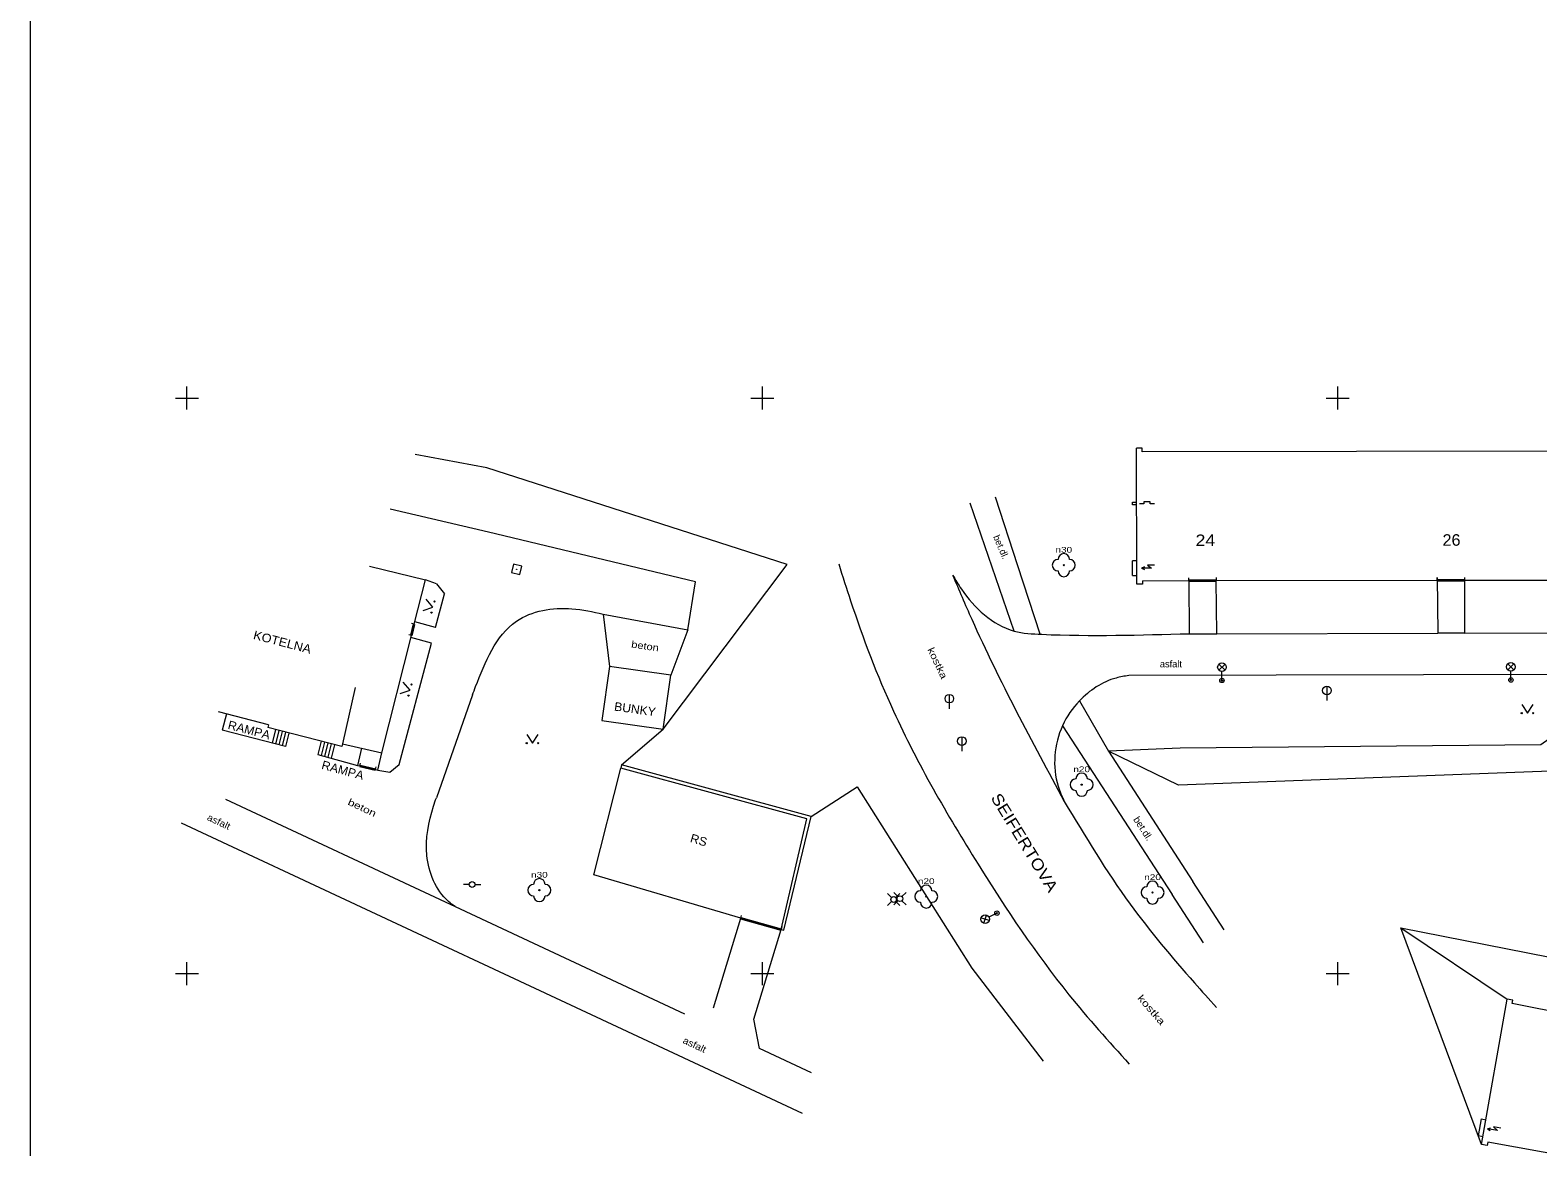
# Model space of a CAD drawing. Extents: x -670514 to -669423, y -1130798 to -1130123.
# Drawn here: x -670513.6 to -670382.6, y -1130515.1 to -1130418 of the extents above; entities that cross this region are included whole.
import ezdxf
from ezdxf.enums import TextEntityAlignment as Align

# ---------------------------------------------------------------- set-up
doc = ezdxf.new("R2010")
doc.units = 0
doc.header["$LTSCALE"] = 0.24
for name, color, linetype, lineweight in [('10', 7, 'Continuous', 13), ('11', 7, 'Continuous', 13), ('14', 7, 'Continuous', 13), ('22', 7, 'Continuous', 13), ('24', 7, 'Continuous', 13), ('26', 7, 'Continuous', 13), ('27', 7, 'Continuous', 13), ('28', 7, 'Continuous', 13), ('31', 7, 'Continuous', 13), ('33', 7, 'Continuous', 13), ('36', 7, 'Continuous', 13), ('45', 7, 'Continuous', 13), ('5', 7, 'Continuous', 13), ('6', 7, 'Continuous', 13), ('60', 7, 'Continuous', 13), ('61', 7, 'Continuous', 13), ('7', 7, 'Continuous', 13), ('8', 7, 'Continuous', 13)]:
    doc.layers.add(name, color=color, linetype=linetype, lineweight=lineweight)
for name, color, linetype in [('40', 7, 'Continuous'), ('41', 7, 'Continuous'), ('42', 7, 'Continuous'), ('44', 7, 'Continuous')]:
    doc.layers.add(name, color=color, linetype=linetype)

msp = doc.modelspace()

# ---------------------------------------------------------------- linework, layer by layer
at = {"layer": '10'}
for p, q in [((-670430.034, -1130464.686), (-670431.936, -1130459.135)), ((-670428.132, -1130470.237), (-670430.034, -1130464.686)), ((-670391.371, -1130465.583), (-670391.319, -1130470.435)), ((-670478.311, -1130466.135), (-670479.288, -1130465.803)), ((-670478.311, -1130466.135), (-670477.613, -1130467.004)), ((-670412.947, -1130465.855), (-670412.902, -1130470.474)), ((-670410.522, -1130470.472), (-670410.56, -1130465.852)), ((-670478.392, -1130469.935), (-670477.613, -1130467.004)), ((-670478.392, -1130469.935), (-670480.198, -1130469.455)), ((-670463.839, -1130468.773), (-670463.298, -1130473.326)), ((-670478.751, -1130471.289), (-670480.544, -1130470.813)), ((-670456.489, -1130470.127), (-670457.945, -1130474.07)), ((-670410.522, -1130470.472), (-670391.319, -1130470.435)), ((-670481.55, -1130481.827), (-670478.751, -1130471.289)), ((-670370.322, -1130474.001), (-670418.162, -1130474.105)), ((-670475.195, -1130475.776), (-670478.329, -1130484.72)), ((-670423.921, -1130478.465), (-670414.389, -1130493.139)), ((-670451.042, -1130510.045), (-670500.485, -1130486.945)), ((-670411.665, -1130497.332), (-670414.389, -1130493.139)), ((-670409.882, -1130496.203), (-670412.597, -1130492.004)), ((-670476.71, -1130494.173), (-670456.755, -1130503.484)), ((-670454.244, -1130502.991), (-670451.871, -1130495.185)), ((-670446.512, -1130512.161), (-670451.042, -1130510.045))]:
    msp.add_line(p, q, dxfattribs=at)
for points in [[(-670425.864, -1130470.526), (-670427.805, -1130464.571), (-670429.746, -1130458.616)], [(-670463.839, -1130468.773), (-670456.489, -1130470.127), (-670455.82, -1130465.971), (-670473.809, -1130461.637), (-670482.332, -1130459.664)], [(-670388.979, -1130465.827), (-670388.977, -1130470.429), (-670369.741, -1130470.406), (-670369.731, -1130465.796)], [(-670422.452, -1130476.308), (-670419.92, -1130480.678), (-670412.597, -1130492.004)], [(-670483.411, -1130482.326), (-670482.366, -1130482.497), (-670481.55, -1130481.827)], [(-670445.72, -1130508.635), (-670450.25, -1130506.519), (-670450.738, -1130503.963), (-670448.365, -1130496.157)]]:
    msp.add_lwpolyline(points, dxfattribs=at)
for points in [[(-670443.367, -1130464.39), (-670442.333, -1130467.627), (-670438.614, -1130477.191), (-670431.256, -1130490.506), (-670423.362, -1130501.834), (-670418.12, -1130507.871)], [(-670433.469, -1130465.379), (-670432.706, -1130466.601), (-670428.132, -1130470.237), (-670425.728, -1130470.526), (-670412.902, -1130470.474)], [(-670475.195, -1130475.776), (-670474.917, -1130475.064), (-670471.377, -1130469.388), (-670466.544, -1130468.3), (-670463.839, -1130468.773)], [(-670418.162, -1130474.105), (-670419.264, -1130474.323), (-670422.452, -1130476.308), (-670423.921, -1130478.465), (-670424.302, -1130483.718), (-670423.768, -1130485.048)], [(-670476.71, -1130494.173), (-670477.282, -1130493.729), (-670479.155, -1130489.729), (-670478.572, -1130485.464), (-670478.329, -1130484.72)], [(-670423.768, -1130485.048), (-670418.049, -1130493.957), (-670412.462, -1130500.796), (-670410.539, -1130502.947)]]:
    msp.add_spline(points, degree=3, dxfattribs=at)
at = {"layer": '11'}
for p, q in [((-670412.902, -1130470.474), (-670410.522, -1130470.472)), ((-670388.977, -1130470.429), (-670391.319, -1130470.435)), ((-670496.665, -1130484.862), (-670476.71, -1130494.173))]:
    msp.add_line(p, q, dxfattribs=at)
msp.add_spline([(-670433.469, -1130465.379), (-670431.81, -1130469.212), (-670423.768, -1130485.048)], degree=3, dxfattribs=at)
at = {"layer": '14'}
for p, q in [((-670413.708, -1130480.415), (-670419.92, -1130480.678)), ((-670413.849, -1130483.645), (-670419.92, -1130480.678)), ((-670394.529, -1130496.029), (-670385.292, -1130502.232))]:
    msp.add_line(p, q, dxfattribs=at)
for points in [[(-670462.23, -1130481.857), (-670458.615, -1130478.765), (-670447.86, -1130464.457), (-670473.931, -1130456.068), (-670480.18, -1130454.91)], [(-670360.693, -1130478.162), (-670377.039, -1130476.373), (-670382.363, -1130480.113), (-670413.708, -1130480.415)], [(-670376.288, -1130477.847), (-670379.229, -1130482.342), (-670413.849, -1130483.645)], [(-670445.764, -1130486.359), (-670441.755, -1130483.772), (-670431.797, -1130499.531), (-670425.599, -1130507.614)], [(-670387.512, -1130514.853), (-670394.529, -1130496.029), (-670324.629, -1130509.773)]]:
    msp.add_lwpolyline(points, dxfattribs=at)
at = {"layer": '22'}
for centre in [(-670423.809, -1130464.517), (-670422.257, -1130483.587), (-670469.38, -1130492.753), (-670416.097, -1130492.96), (-670435.762, -1130493.306)]:
    msp.add_circle(centre, 0.05, dxfattribs=at)
for centre, start, end in [((-670424.309, -1130464.517), 90, 270), ((-670423.809, -1130464.017), 0, 180), ((-670423.309, -1130464.517), 270, 90), ((-670423.809, -1130465.017), 180, 0), ((-670422.257, -1130483.087), 0, 180), ((-670422.757, -1130483.587), 90, 270), ((-670421.757, -1130483.587), 270, 90), ((-670422.257, -1130484.087), 180, 0), ((-670469.38, -1130492.253), 0, 180), ((-670469.88, -1130492.753), 90, 270), ((-670468.88, -1130492.753), 270, 90), ((-670436.262, -1130493.306), 90, 270), ((-670435.762, -1130492.806), 0, 180), ((-670435.262, -1130493.306), 270, 90), ((-670416.597, -1130492.96), 90, 270), ((-670416.097, -1130492.46), 0, 180), ((-670415.597, -1130492.96), 270, 90), ((-670469.38, -1130493.253), 180, 0), ((-670435.762, -1130493.806), 180, 0), ((-670416.097, -1130493.46), 180, 0)]:
    msp.add_arc(centre, 0.5, start, end, dxfattribs=at)
at = {"layer": '24'}
for p, q in [((-670417.849, -1130465.415), (-670417.85, -1130464.146)), ((-670417.472, -1130464.146), (-670417.849, -1130464.146)), ((-670417.848, -1130465.416), (-670417.467, -1130465.415))]:
    msp.add_line(p, q, dxfattribs=at)
for points in [[(-670417.487, -1130459.284), (-670417.845, -1130459.285), (-670417.846, -1130459.032), (-670417.487, -1130459.031)], [(-670415.938, -1130459.186), (-670416.306, -1130459.186), (-670416.307, -1130459.003), (-670416.859, -1130459.006), (-670416.859, -1130459.189), (-670417.227, -1130459.191)], [(-670415.923, -1130464.528), (-670416.549, -1130464.529), (-670416.174, -1130464.779), (-670417.049, -1130464.78)], [(-670416.804, -1130464.67), (-670417.049, -1130464.78), (-670416.804, -1130464.89)], [(-670387.393, -1130514.176), (-670387.786, -1130514.106), (-670387.527, -1130512.629), (-670387.133, -1130512.698)], [(-670385.843, -1130513.433), (-670386.459, -1130513.324), (-670386.133, -1130513.636), (-670386.995, -1130513.484)], [(-670386.735, -1130513.418), (-670386.995, -1130513.484), (-670386.773, -1130513.635)]]:
    msp.add_lwpolyline(points, dxfattribs=at)
at = {"layer": '26'}
msp.add_lwpolyline([(-670471.806, -1130465.144), (-670471.079, -1130465.331), (-670470.892, -1130464.604), (-670471.619, -1130464.417)], close=True, dxfattribs=at)
msp.add_circle((-670471.3489, -1130464.874), 0.02, dxfattribs=at)
at = {"layer": '27'}
for p, q in [((-670433.757, -1130475.74), (-670433.757, -1130476.99)), ((-670400.941, -1130475.027), (-670400.941, -1130476.277)), ((-670432.669, -1130479.421), (-670432.669, -1130480.671))]:
    msp.add_line(p, q, dxfattribs=at)
for centre in [(-670433.7566, -1130476.1151), (-670400.9406, -1130475.4021), (-670432.6686, -1130479.7961)]:
    msp.add_circle(centre, 0.375, dxfattribs=at)
at = {"layer": '28'}
for p, q in [((-670475.466, -1130492.262), (-670475.966, -1130492.262)), ((-670474.966, -1130492.262), (-670474.466, -1130492.262))]:
    msp.add_line(p, q, dxfattribs=at)
msp.add_circle((-670475.2163, -1130492.2622), 0.25, dxfattribs=at)
at = {"layer": '31'}
for p, q in [((-670439.124, -1130493.034), (-670438.769, -1130493.389)), ((-670438.581, -1130492.961), (-670438.226, -1130493.316)), ((-670438.415, -1130493.388), (-670438.061, -1130493.035)), ((-670437.872, -1130493.315), (-670437.518, -1130492.962)), ((-670438.769, -1130493.742), (-670439.122, -1130494.096)), ((-670438.226, -1130493.669), (-670438.579, -1130494.023)), ((-670438.416, -1130493.741), (-670438.061, -1130494.096)), ((-670437.873, -1130493.668), (-670437.518, -1130494.023))]:
    msp.add_line(p, q, dxfattribs=at)
for centre in [(-670438.5918, -1130493.5656), (-670438.0488, -1130493.4926)]:
    msp.add_circle(centre, 0.25, dxfattribs=at)
at = {"layer": '33'}
for p, q in [((-670410.329, -1130473.12), (-670409.799, -1130473.65)), ((-670410.329, -1130473.65), (-670409.799, -1130473.12)), ((-670385.222, -1130473.078), (-670384.692, -1130473.608)), ((-670385.222, -1130473.608), (-670384.692, -1130473.078)), ((-670410.064, -1130474.535), (-670410.064, -1130473.76)), ((-670384.957, -1130474.493), (-670384.957, -1130473.718)), ((-670430.293, -1130495.39), (-670431.006, -1130495.159)), ((-670430.765, -1130495.631), (-670430.534, -1130494.918)), ((-670429.625, -1130494.752), (-670430.315, -1130495.104))]:
    msp.add_line(p, q, dxfattribs=at)
for centre, radius in [((-670410.064, -1130473.385), 0.375), ((-670384.957, -1130473.343), 0.375), ((-670410.064, -1130474.535), 0.19), ((-670410.064, -1130474.535), 0.05), ((-670384.957, -1130474.493), 0.19), ((-670384.957, -1130474.493), 0.05), ((-670430.6494, -1130495.2745), 0.375), ((-670429.625, -1130494.752), 0.19), ((-670429.625, -1130494.752), 0.05)]:
    msp.add_circle(centre, radius, dxfattribs=at)
at = {"layer": '36'}
for points in [[(-670479.477, -1130468.448), (-670478.624, -1130468.157), (-670479.22, -1130467.481)], [(-670481.472, -1130475.662), (-670480.619, -1130475.371), (-670481.215, -1130474.695)], [(-670384.022, -1130476.622), (-670383.522, -1130477.372), (-670383.022, -1130476.622)], [(-670470.482, -1130479.226), (-670469.982, -1130479.976), (-670469.482, -1130479.226)]]:
    msp.add_lwpolyline(points, dxfattribs=at)
for centre in [(-670478.4956, -1130467.6738), (-670478.7524, -1130468.6402), (-670480.7474, -1130475.8542), (-670480.4906, -1130474.8878), (-670384.022, -1130477.372), (-670383.022, -1130477.372), (-670470.482, -1130479.976), (-670469.482, -1130479.976)]:
    msp.add_circle(centre, 0.05, dxfattribs=at)
at = {"layer": '5'}
for p, q in [((-670417.003, -1130454.36), (-670417.503, -1130454.362)), ((-670417.465, -1130466.173), (-670417.503, -1130454.362)), ((-670417.002, -1130454.66), (-670417.003, -1130454.36)), ((-670356.25, -1130454.589), (-670417.002, -1130454.66)), ((-670484.139, -1130464.59), (-670479.288, -1130465.803)), ((-670480.25, -1130469.649), (-670479.288, -1130465.803)), ((-670416.965, -1130466.171), (-670417.465, -1130466.173)), ((-670416.966, -1130465.871), (-670412.947, -1130465.855)), ((-670416.966, -1130465.871), (-670416.965, -1130466.171)), ((-670410.56, -1130465.852), (-670391.371, -1130465.833)), ((-670388.979, -1130465.827), (-670369.731, -1130465.796)), ((-670485.376, -1130475.158), (-670486.493, -1130480.032)), ((-670492.921, -1130478.391), (-670497.249, -1130477.262)), ((-670496.56, -1130477.442), (-670496.928, -1130478.851)), ((-670492.921, -1130478.391), (-670492.983, -1130478.633)), ((-670486.555, -1130480.274), (-670492.983, -1130478.633)), ((-670491.435, -1130480.279), (-670496.928, -1130478.851)), ((-670492.297, -1130478.807), (-670492.597, -1130479.981)), ((-670492.006, -1130478.882), (-670492.306, -1130480.056)), ((-670491.716, -1130478.956), (-670492.016, -1130480.13)), ((-670491.425, -1130479.03), (-670491.725, -1130480.204)), ((-670491.135, -1130479.105), (-670491.435, -1130480.279)), ((-670488.339, -1130479.819), (-670488.635, -1130480.979)), ((-670488.048, -1130479.893), (-670488.344, -1130481.053)), ((-670487.757, -1130479.967), (-670488.053, -1130481.127)), ((-670487.466, -1130480.041), (-670487.762, -1130481.201)), ((-670486.493, -1130480.032), (-670486.555, -1130480.274)), ((-670488.635, -1130480.979), (-670485.184, -1130481.916)), ((-670487.176, -1130480.115), (-670487.472, -1130481.275)), ((-670484.839, -1130480.411), (-670485.184, -1130481.916)), ((-670483.411, -1130482.326), (-670483.077, -1130480.815)), ((-670485.184, -1130481.916), (-670484.989, -1130481.961)), ((-670483.605, -1130482.28), (-670483.411, -1130482.326)), ((-670387.512, -1130514.853), (-670385.292, -1130502.232)), ((-670384.8, -1130502.319), (-670385.292, -1130502.232)), ((-670384.852, -1130502.614), (-670384.8, -1130502.319)), ((-670325.201, -1130514.395), (-670384.852, -1130502.614)), ((-670387.02, -1130514.94), (-670387.512, -1130514.853)), ((-670386.968, -1130514.645), (-670387.02, -1130514.94)), ((-670327.162, -1130525.423), (-670386.968, -1130514.645))]:
    msp.add_line(p, q, dxfattribs=at)
msp.add_lwpolyline([(-670486.493, -1130480.032), (-670483.077, -1130480.815), (-670480.493, -1130470.62)], dxfattribs=at)
msp.add_lwpolyline([(-670457.945, -1130474.07), (-670463.298, -1130473.326), (-670463.965, -1130478.006), (-670458.615, -1130478.765)], close=True, dxfattribs=at)
at = {"layer": '6'}
for p, q in [((-670412.947, -1130465.855), (-670412.947, -1130465.605)), ((-670410.56, -1130465.602), (-670410.56, -1130465.852)), ((-670391.371, -1130465.833), (-670391.371, -1130465.583)), ((-670388.979, -1130465.577), (-670388.979, -1130465.827)), ((-670480.493, -1130470.62), (-670480.735, -1130470.559)), ((-670480.25, -1130469.649), (-670480.492, -1130469.589)), ((-670484.989, -1130481.961), (-670484.932, -1130481.717)), ((-670483.605, -1130482.28), (-670483.549, -1130482.037))]:
    msp.add_line(p, q, dxfattribs=at)
at = {"layer": '6', "lineweight": 35}
for p, q in [((-670412.947, -1130465.855), (-670410.56, -1130465.852)), ((-670391.371, -1130465.833), (-670388.979, -1130465.827)), ((-670480.493, -1130470.62), (-670480.25, -1130469.649)), ((-670484.989, -1130481.961), (-670483.605, -1130482.28))]:
    msp.add_line(p, q, dxfattribs=at)
at = {"layer": '60'}
msp.add_lwpolyline([(-670513.627, -1130676.756), (-670103.627, -1130676.756), (-670103.627, -1130389.756), (-670513.627, -1130389.756)], close=True, dxfattribs=at)
at = {"layer": '61'}
for p, q in [((-670500, -1130451), (-670500, -1130449)), ((-670450, -1130451), (-670450, -1130449)), ((-670400, -1130451), (-670400, -1130449)), ((-670501, -1130450), (-670499, -1130450)), ((-670451, -1130450), (-670449, -1130450)), ((-670401, -1130450), (-670399, -1130450)), ((-670500, -1130501), (-670500, -1130499)), ((-670450, -1130501), (-670450, -1130499)), ((-670400, -1130501), (-670400, -1130499)), ((-670501, -1130500), (-670499, -1130500)), ((-670451, -1130500), (-670449, -1130500)), ((-670401, -1130500), (-670399, -1130500))]:
    msp.add_line(p, q, dxfattribs=at)
at = {"layer": '7'}
for p, q in [((-670464.644, -1130491.409), (-670462.309, -1130482.146)), ((-670462.23, -1130481.857), (-670462.309, -1130482.146)), ((-670446.129, -1130486.57), (-670462.309, -1130482.146)), ((-670445.764, -1130486.359), (-670462.23, -1130481.857)), ((-670448.365, -1130496.157), (-670446.129, -1130486.57)), ((-670448.123, -1130496.221), (-670445.764, -1130486.359)), ((-670451.871, -1130495.185), (-670464.644, -1130491.409)), ((-670448.365, -1130496.157), (-670448.123, -1130496.221))]:
    msp.add_line(p, q, dxfattribs=at)
at = {"layer": '8'}
for p, q in [((-670451.871, -1130495.185), (-670451.804, -1130494.944)), ((-670448.298, -1130495.916), (-670448.365, -1130496.157))]:
    msp.add_line(p, q, dxfattribs=at)
at = {"layer": '8', "lineweight": 35}
msp.add_line((-670451.871, -1130495.185), (-670448.365, -1130496.157), dxfattribs=at)

# ---------------------------------------------------------------- texts
at = {"layer": '22', "width": 1.3}
for s, p in [('n30', (-670423.8085, -1130463.431)), ('n20', (-670422.2565, -1130482.501)), ('n30', (-670469.3795, -1130491.667)), ('n20', (-670435.7615, -1130492.22)), ('n20', (-670416.0965, -1130491.874))]:
    msp.add_text(s, height=0.499, dxfattribs=at).set_placement(p, align=Align.CENTER)
at = {"layer": '40'}
for s, rotation, p in [('bet.dl.', 293.404, (-670429.5345, -1130463.0568)), ('asfalt', 0.125, (-670414.5022, -1130473.3974))]:
    msp.add_text(s, height=0.6, rotation=rotation, dxfattribs=at).set_placement(p, align=Align.CENTER)
for s, rotation, width, p in [('beton', 352.087, 1.2, (-670460.2318, -1130471.8406)), ('kostka', 295.319, 1.25, (-670435.0553, -1130473.1532)), ('beton', 334.986, 1.3, (-670484.9049, -1130485.8563)), ('asfalt', 334.958, 1.1, (-670497.358, -1130487.0791)), ('bet.dl.', 303.007, 1.05, (-670417.1726, -1130487.5676)), ('kostka', 310.968, 1.35, (-670416.423, -1130503.3438)), ('asfalt', 334.958, 1.1, (-670456.014, -1130506.4611))]:
    msp.add_text(s, height=0.6, rotation=rotation, dxfattribs=dict(at, width=width)).set_placement(p, align=Align.CENTER)
at = {"layer": '41'}
for s, rotation, width, p in [('KOTELNA', 345.38, 1.1, (-670491.8047, -1130471.5619)), ('BUNKY', 351.925, 1.05, (-670461.1192, -1130477.3992)), ('RS', 343.531, 1.05, (-670455.6333, -1130488.7631))]:
    msp.add_text(s, height=0.75, rotation=rotation, dxfattribs=dict(at, width=width)).set_placement(p, align=Align.CENTER)
at = {"layer": '42', "width": 1.05}
for rotation, p in [(345.428, (-670494.6944, -1130479.1984)), (344.81, (-670486.5593, -1130482.6903))]:
    msp.add_text('RAMPA', height=0.75, rotation=rotation, dxfattribs=at).set_placement(p, align=Align.CENTER)
at = {"layer": '44'}
for s, rotation, width, p in [('24', 0.072, 1.15, (-670411.5061, -1130462.8529)), ('26', 0.144, 1.05, (-670390.1168, -1130462.83))]:
    msp.add_text(s, height=1, rotation=rotation, dxfattribs=dict(at, width=width)).set_placement(p, align=Align.CENTER)
at = {"layer": '45', "width": 1.15}
msp.add_text('SEIFERTOVA', height=1, rotation=301.445, dxfattribs=at).set_placement((-670427.6507, -1130488.8832), align=Align.CENTER)

doc.saveas('drawing.dxf')
